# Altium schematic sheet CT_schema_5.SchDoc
size 368 x 245 mm
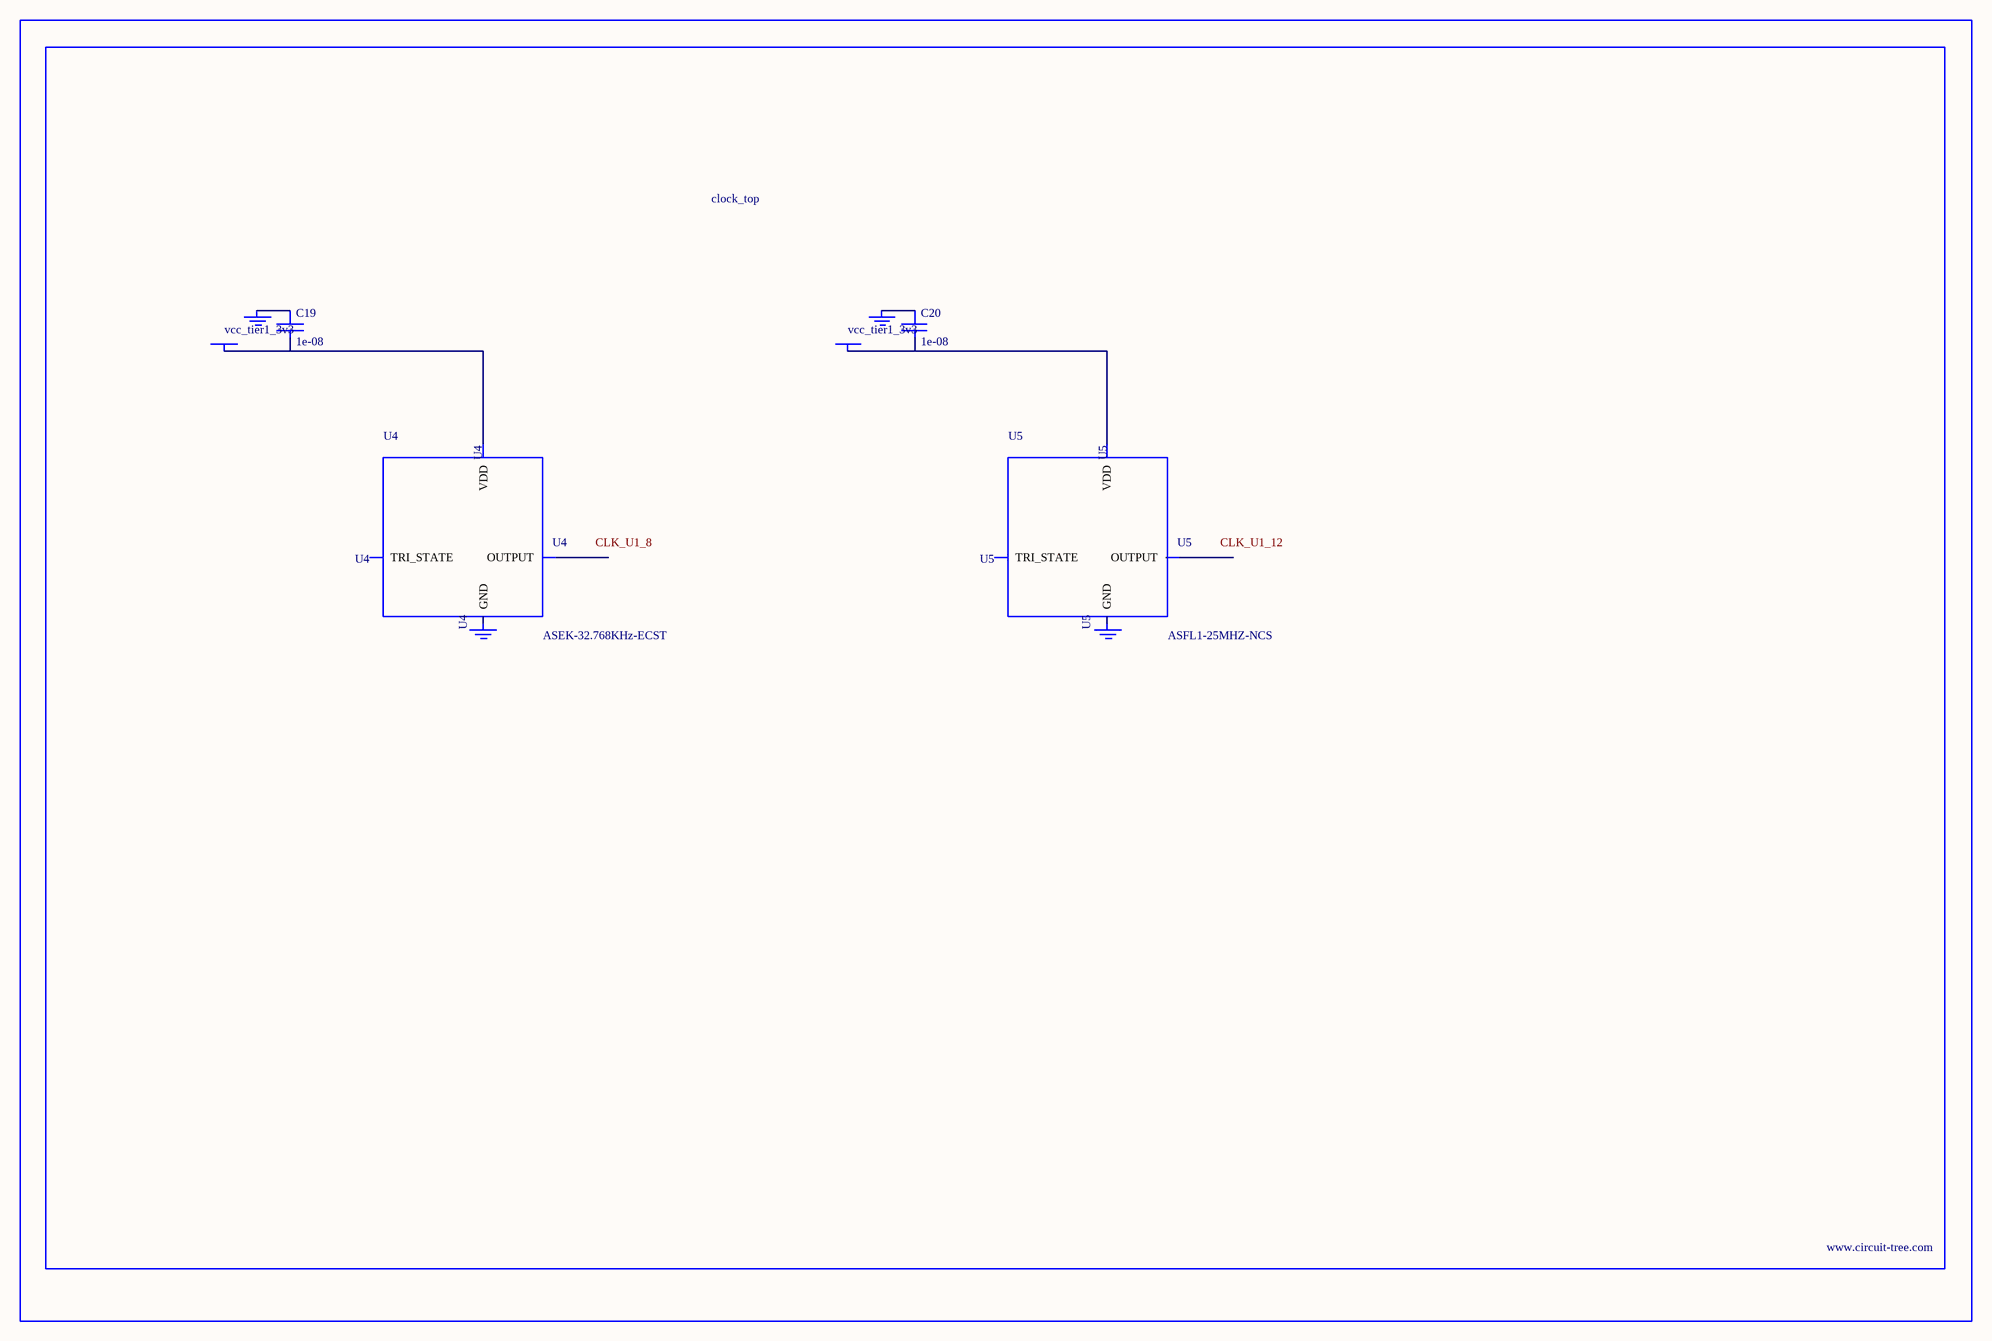
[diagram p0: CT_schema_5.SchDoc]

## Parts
BORDER4  (no value)
C19  1e-08  [C0402]
C20  1e-08  [C0402]
GND_INSTANCE_4_0  (no value)
GND_INSTANCE_4_1  (no value)
GND_INSTANCE_4_2  (no value)
GND_INSTANCE_4_3  (no value)
POWER_INSTANCE_4_0  vcc_tier1_3v3
POWER_INSTANCE_4_1  vcc_tier1_3v3
U4  ASEK-32.768KHz-ECST  [ASEK]
U5  ASFL1-25MHZ-NCS  [ASFL1]

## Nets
NetC19_1: C19.1 GND_INSTANCE_4_0.0(GND)
NetC19_2: C19.2 POWER_INSTANCE_4_0.0(PWR) U4.4(VDD)
NetC20_1: C20.1 GND_INSTANCE_4_2.0(GND)
NetC20_2: C20.2 POWER_INSTANCE_4_1.0(PWR) U5.4(VDD)

Not connected (* = marked no-connect by the designer): GND_INSTANCE_4_1 0(GND); GND_INSTANCE_4_3 0(GND); U4 1(TRI_STATE) 2(GND) 3(OUTPUT); U5 1(TRI_STATE) 2(GND) 3(OUTPUT)

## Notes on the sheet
- Labels drawn without touching a wire or pin: CLK_U1_8, CLK_U1_12

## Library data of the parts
BORDER4 = BORDER_PAGE4
C19 C20 = C0402C103K3RAC
GND_INSTANCE_4_0-GND_INSTANCE_4_3 = GND
POWER_INSTANCE_4_0 POWER_INSTANCE_4_1 = PWR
